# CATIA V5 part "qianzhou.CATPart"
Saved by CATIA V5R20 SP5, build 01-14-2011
Part number: 前轴
Bounding box of the stored display mesh (mm): x -32.5 to 32.5, y -10.463 to 167.423, z -126.767 to 75
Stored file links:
  E:\180512116\zp\20190505\180512116赵克君\qianzhou.CATPart
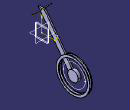
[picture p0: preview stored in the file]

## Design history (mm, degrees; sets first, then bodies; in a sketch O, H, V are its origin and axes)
Body1 (main body)
  Sketch1 on yz-plane, origin (0, 0, 0), H (0, 1, 0), V (0, 0, 1)
    line L1 (120, -73.7307) -> (120, -75)
    line L2 (120, -75) -> (100.1643, -75)
    line L3 (-10.4631, 75) -> (10.3087, 75)
    point P1 (120, 75)
    point P3 (-120, -75)
    line L4 (-10.4631, 75) -> (100.1643, -75)
    line L5 (10.3087, 75) -> (120, -73.7307)
    vertical: L1 V
    horizontal: L2 H, L3 H
    equidistance: L2 L3 O
    parallelism: L5 L4
  Pad1: profile Sketch1, direction (1, 0, 0), length 2.5, mirrored extent
  Sketch2 on yz-plane, origin (0, 0, 0), H (0, 1, 0), V (0, 0, 1)
    circle A1 centre (0, 70.01) radius 1.259
    point P1 (0, 70.01)
    radius A1 = 1.259
    coincidence: P1 V
  Pad2: profile Sketch2, direction (1, 0, 0), length 32.5, mirrored extent
  Sketch3 on yz-plane, origin (0, 0, 0), H (0, 1, 0), V (0, 0, 1)
    circle A1 centre (110.5382, -69.9655) radius 17.7988
  Pad3: profile Sketch3, direction (1, 0, 0), length 5, mirrored extent
  Sketch4 on yz-plane, origin (0, 0, 0), H (0, 1, 0), V (0, 0, 1)
    circle A1 centre (110.1718, -70.2215) radius 37.2105
  Plane1: type Offset, RefPlane yz-plane, Offset 2.5
  Plane2: type Offset, RefPlane yz-plane, Offset 2.5, reversed
  Sketch5 on Plane1, origin (2.5, 0, 0), H (0, 1, 0), V (0, 0, 1)
    circle A1 centre (110.6496, -70.1866) radius 56.7738
    circle A2 centre (110.6496, -70.1866) radius 49.6976
  Pad4: profile Sketch5, direction (1, 0, 0), length 2.5
  Sketch6 on Plane2, origin (-2.5, 0, 0), H (0, 1, 0), V (0, 0, 1)
    circle A1 centre (109.8483, -69.6378) radius 49.18
    circle A2 centre (109.8483, -69.6378) radius 56.6348
  Pad5: profile Sketch6, direction (-1, 0, 0), length 2.5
